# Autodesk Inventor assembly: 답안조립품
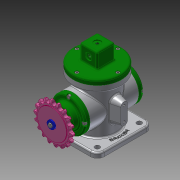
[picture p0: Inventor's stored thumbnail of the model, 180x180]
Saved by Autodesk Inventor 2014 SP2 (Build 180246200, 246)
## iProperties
Created: 2021-03
Part Number: 답안조립품
Document SubType Name: Assembly
Designer: 거성
Author: 거성
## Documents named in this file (19)
- C:\Users\거성\Desktop\710306V1019\답안조립품.iam
- C:\Users\거성\Desktop\710306V1019\본체.ipt
- C:\Users\거성\Desktop\710306V1019\뒤커버.ipt
- C:\Users\거성\Desktop\710306V1019\앞커버.ipt
- C:\Users\거성\Desktop\710306V1019\베어링 17 x 40 x 12.ipt
- C:\Users\거성\Desktop\710306V1019\오일 실 17 30 8.ipt
- C:\Users\거성\Desktop\710306V1019\편심축.ipt
- C:\Users\거성\Desktop\710306V1019\키 4 x 4 x 12.ipt
- C:\Users\거성\Desktop\710306V1019\스프로킷.ipt
- C:\Users\거성\Desktop\710306V1019\덮개.ipt
- C:\Users\거성\Desktop\710306V1019\볼트 M4 x 10.ipt
- C:\Users\거성\Desktop\710306V1019\링크.ipt
- C:\Users\거성\Desktop\710306V1019\슬라이더.ipt
- C:\Users\거성\Desktop\710306V1019\클레비스 핀 6 x 22.ipt
- 클레비스 핀 6 x 22.ipt
- C:\Users\거성\Desktop\710306V1019\E-링.ipt
- C:\Users\거성\Desktop\710306V1019\볼트 M4 x 8.ipt
- C:\Users\거성\Desktop\710306V1019\와셔 4x16.ipt
- C:\Users\거성\Desktop\710306V1019\멈춤나사 M3.ipt
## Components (1 placed, 1 different names)
1. E-링:1
